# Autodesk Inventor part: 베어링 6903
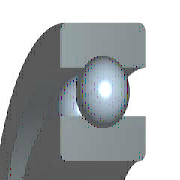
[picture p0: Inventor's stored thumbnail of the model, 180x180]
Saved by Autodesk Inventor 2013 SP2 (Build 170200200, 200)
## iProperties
Created: 2012-02
Part Number: 베어링 6903
Material: 강철, 연강
Description: 깊은 그루브 볼 베어링
Document SubType Name: Modeling
Standard: KS B 2023
Designer: mduedu
Standards Organization: KS
Language: ko-KR
Size Designation: 6003 - 17 x 35 x 10
Categories: <MemberInstance><Categories><Category DisplayName="샤프트 부품" InternalName="7f7aeb1f-a693-4053-b835-cee3144e0d98" Mnemonic="SHFT"><Category DisplayName="베어링" Inter
Density: 1 g/cm^3
IsCustomPart: 1
Author: mduedu
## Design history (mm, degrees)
sketch "스케치" dims "d0" = 3.38 (= -0.26 x WD + 0.26 x BD)
  geometry: L1 (1.81, 11.75)-(5.19, 11.75); L2 (3.5, 11.75)-(3.5, 10.06); L3 (3.5, 11.75)-(3.5, 13.44); L4 (2.244, 10.619)-(0, 10.619); L5 (0, 8.5)-(7, 8.5); L6 (2.244, 12.881)-(0, 12.881); L7 (0, 15)-(7, 15); L8 (7, 8.5)-(7, 10.619); L9 (4.756, 10.619)-(7, 10.619); L10 (4.756, 12.881)-(7, 12.881); L11 (7, 15)-(7, 12.881); L12 (-2, 0)-(12, 0) reference; L13 (0, 7.2)-(0, 16.3) reference; 1 other entity
  constraints: 22 end point, 4 point on line, 2 collinear, 2 perpendicular, 2 symmetric about line, 1 midpoint, 1 parallel, 14 other
  dimensions: "d9" = 17 diameter of L5 L12 (= WD); "d11" = 30 diameter of L7 L12 (= BD); "d12" = 7 distance between parallel lines of L8 L13 (= KB); "d13" = 21.238 diameter of L9 L12 (= 0.326 x BD + 0.674 x WD)
revolve "본체" stored, may be unused: angle "d6" = 90 deg
revolve "볼" stored, may be unused: angle "d7" = 90 deg
pattern_circular "IDS_ARRAYBALL[SIMPL:T]" dims angle "d3" = 360 deg
body "Solid1"
fillet "모깎기1" dims "d1" = 0.3 (= KRS)
other parameters: "WD" = 17 [user parameter; used in 5 equation terms], "BD" = 30 [user parameter; used in 5 equation terms], "KB" = 7 [user parameter; used in 1 equation term], "KRS" = 0.3 [user parameter; used in 1 equation term], "d4" = 0, "d5" = 0, "d8" = 0, "d14" = 0, "d15" = 0, "BBA" = 0 [user parameter], "BC0" = 3250000 [user parameter], "BC" = 6050000 [user parameter], "BR" = 15 (= 0.5 x BD) [user parameter], "WR" = 8.5 (= 0.5 x WD) [user parameter]
